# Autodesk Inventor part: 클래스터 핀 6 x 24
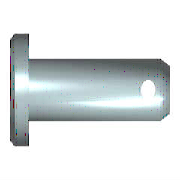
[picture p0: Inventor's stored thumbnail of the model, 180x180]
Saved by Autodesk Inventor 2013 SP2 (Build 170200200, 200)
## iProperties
IsCustomPart: 1
Created: 2012-02
Part Number: 클래스터 핀 6 x 24
Material: 강철
Description: 머리가 있는 클레비스 핀
Document SubType Name: Modeling
Standard: ISO 2341
Designer: mduedu
Standard Revision: Second edition 1986-11-01
Standards Organization: ISO
Language: ko-KR
Size Designation: B - 6 x 24
Categories: <MemberInstance><Categories><Category DisplayName="조임쇠" InternalName="e4da775c-781d-43d5-af7c-5136215cf5a6" Mnemonic="FSTN"><Category DisplayName="핀" InternalNa
Density: 7.85 g/cm^3
Author: mduedu
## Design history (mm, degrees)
sketch "스케치1"
  geometry: L1 (-2, 0)-(-2, 5); L2 (-2, 5)-(0, 5); L3 (0, 5)-(0, 3); L4 (0, 3)-(24, 3); L5 (24, 3)-(24, 0); L6 (-2, 0)-(24, 0); L7 (-4, 0)-(17, 0) reference; L8 (0, -0.98)-(0, 3.08) reference; C1 r 0.8 at (20.8, 0)
  constraints: 12 end point, 3 parallel, 2 collinear, 2 perpendicular, 1 centre point, 1 point on line, 1 vertical
  dimensions: "d0" = 6 diameter of L4 L6 (= NND); "d1" = 10 diameter of L2 L6 (= KOD); "d2" = 2 distance of L1.end L2.end (= KOH); "d3" = 24 distance of L3.end L4.end (= NLG); "d5" = 3.2 distance from line of L5 C1.centre (= DIST); "d6" = 1.6 diameter of C1 (= BOR)
revolve "본체" stored, may be unused: angle "d4" = 90 deg
extrude "구멍" cut sketch "스케치1" stored distance "d7" = 6 (= NND); taper "d8" = 0 deg
workaxis "Work Axis1"
workplane "Work Plane1"
body "Solid1"
chamfer "모따기1" distance "d9" = 1 (= PHH2); stored, may be unused: angle "d10" = 45 deg (= FAWI2), second distance "d16" = 1 (= PHH2)
chamfer "모따기2" distance "d11" = 2 (= PHH1); stored, may be unused: angle "d12" = 30 deg (= FAWI1), second distance "d17" = 2 (= PHH1)
other parameters: "PHH1" = 2 [user parameter; used in 2 equation terms], "PHH2" = 1 [user parameter; used in 2 equation terms], "KOD" = 10 [user parameter; used in 1 equation term], "KOH" = 2 [user parameter; used in 1 equation term], "NND" = 6 [user parameter; used in 2 equation terms], "FAWI1" = 30 deg [user parameter; used in 1 equation term], "FAWI2" = 45 deg [user parameter; used in 1 equation term], "DIST" = 3.2 [user parameter; used in 1 equation term], "BOR" = 1.6 [user parameter; used in 1 equation term], "NLG" = 24 [user parameter; used in 1 equation term], "d13" = 0, "d14" = 0, "d27" = 0, "d28" = 0, "d29" = 0, "d30" = 0, "d31" = 0
